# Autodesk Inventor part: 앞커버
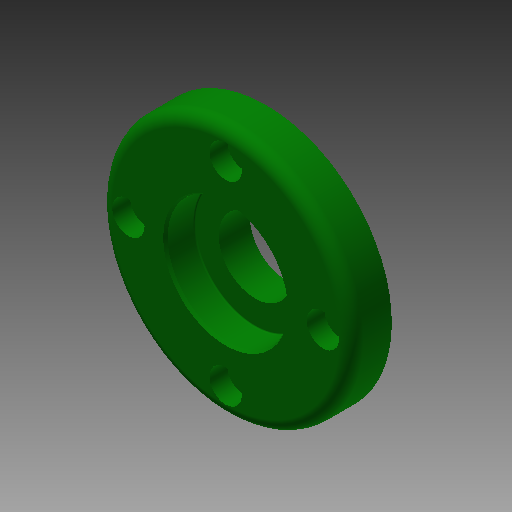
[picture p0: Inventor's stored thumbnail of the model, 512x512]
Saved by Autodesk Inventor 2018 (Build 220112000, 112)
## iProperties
Created: 2015-09
Part Number: 앞커버
Material: 알루미늄 6061
Document SubType Name: Modeling
Designer: mduedu
Density: 1 g/cm^3
Appearance: 진녹색
Author: mduedu
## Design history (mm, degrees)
sketch "스케치1"
  geometry: L1 (0, 7.5)-(0, -7.5); L2 (0, 7.5)-(31, 7.5); L3 (31, 7.5)-(31, -2.5); L4 (31, -2.5)-(17.5, -2.5); L5 (17.5, -2.5)-(17.5, -7.5); L6 (17.5, -7.5)-(0, -7.5); 2 further points
  constraints: 12 end point, 2 parallel, 2 perpendicular, 1 coincident, 1 horizontal, 1 midpoint, 1 vertical
  dimensions: "d0" = 15 distance of L1.start L1.end; "d1" = 62 diameter of L3 L1; "d2" = 35 diameter of L5 L1; "d3" = 10 distance of L2.end L3.end
revolve "회전1" sketch "스케치1" stored, may be unused: angle "d4" = 90 deg
hole "구멍1" diameter "d7" = 30; stored, may be unused: countersink angle "d11" = 90 deg, drill point angle "d13" = 0 deg; dims "d8" = 6, "d9" = 4, "d10" = 2, "d12" = 7.3, "d46" = 10, "d47" = 10
hole "구멍2" diameter "d16" = 18; stored, may be unused: countersink angle "d20" = 90 deg, drill point angle "d22" = 0 deg; dims "d14" = 10, "d15" = 10, "d17" = 6, "d18" = 4, "d19" = 2, "d21" = 7.3
fillet "모깎기2" dims "d48" = 3
chamfer "모따기2" distance "d26" = 0.7; stored, may be unused: second distance "d27" = 2, angle "d28" = 30 deg
fillet "모깎기1" dims "d29" = 0.3
sketch "스케치4" dims "d49" = 48
  geometry: 3 further points
  constraints: 2 vertical alignment, 1 coincident, 2 other
hole "구멍4" sketch "스케치4" at (0, 24) diameter "d50" = 4.5; stored, may be unused: countersink angle "d54" = 90 deg, drill point angle "d56" = 118 deg; dims "d51" = 6, "d52" = 8, "d53" = 4.4, "d55" = 8
chamfer "모따기3" distance "d43" = 1; stored, may be unused: second distance "d44" = 2, angle "d45" = 45 deg
node "솔리드1"
pattern_circular "원형 패턴1" dims angle "d58" = 360 deg
